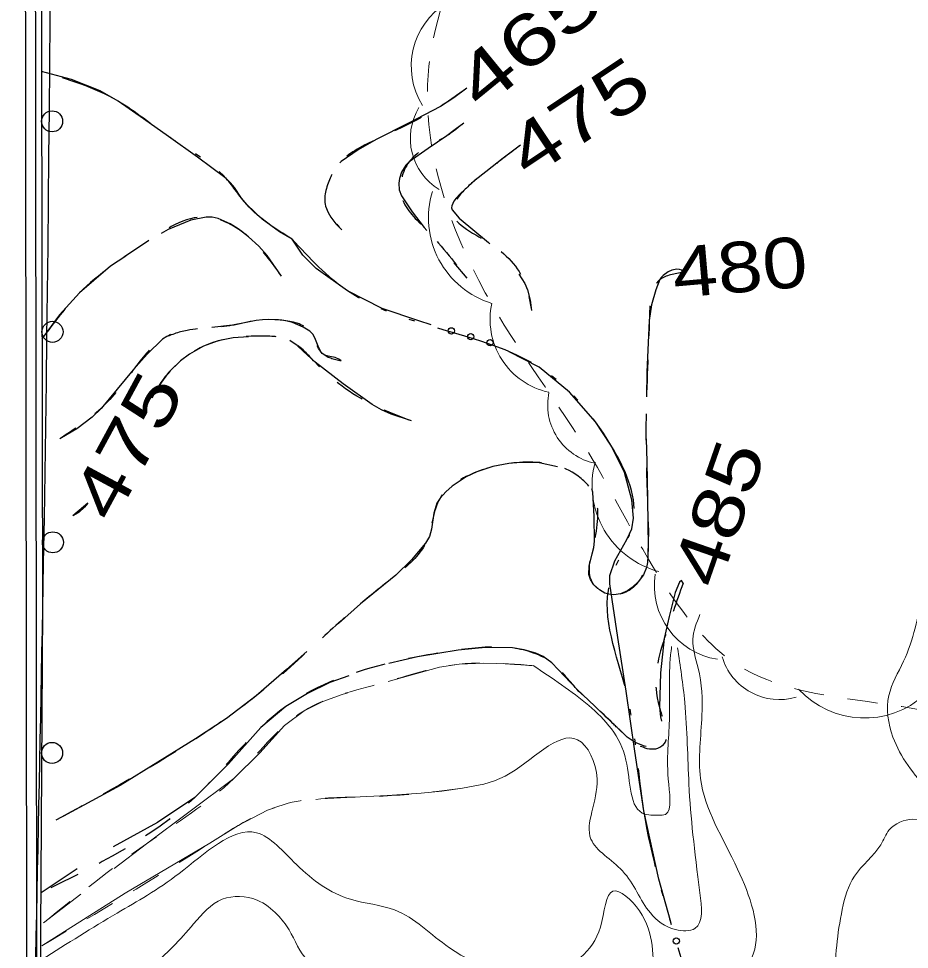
# Model space of a CAD drawing. Extents: x 2362213 to 2366494, y 6968794 to 6978110.
# Drawn here: x 2364480.8 to 2364565.4, y 6970408.1 to 6970496.6 of the extents above; entities that cross this region are included whole.
import ezdxf
from ezdxf.enums import TextEntityAlignment as Align

# ---------------------------------------------------------------- set-up
doc = ezdxf.new("R2010")
doc.units = 0
doc.header["$LTSCALE"] = 1.9
doc.linetypes.add('DASH_DOUBLE_DOT', pattern=[9.2, 5, -1.2, 0.3, -1.2, 0.3, -1.2])
doc.linetypes.add('SHORT_DASHED', pattern=[2.7, 1.5, -1.2])
for name, color, linetype, lineweight in [('2', 7, 'Continuous', 25), ('25', 7, 'Continuous', 25), ('29', 7, 'Continuous', 13), ('31', 7, 'Continuous', 25), ('32', 7, 'Continuous', 25), ('35', 7, 'Continuous', 13), ('36', 7, 'Continuous', 13), ('4', 7, 'Continuous', 25)]:
    doc.layers.add(name, color=color, linetype=linetype, lineweight=lineweight)

msp = doc.modelspace()

# ---------------------------------------------------------------- linework, layer by layer
at = {"layer": '2'}
for points in [[(2364480.853, 6970987.21), (2364481.694, 6970308.696), (2364482.198, 6970284.09)], [(2364481.813, 6970987.209), (2364482.654, 6970308.705), (2364483.158, 6970284.109), (2364483.158, 6970284.077)]]:
    msp.add_lwpolyline(points, dxfattribs=at)
at = {"layer": '25'}
for points in [[(2364506.806, 6970475.613), (2364505.599, 6970476.301), (2364503.978, 6970477.506), (2364502.504, 6970478.892), (2364501.998, 6970479.507), (2364501.329, 6970480.501), (2364500.965, 6970480.967), (2364500.541, 6970481.363), (2364497.821, 6970483.377), (2364495.072, 6970485.351), (2364492.685, 6970487.049), (2364490.279, 6970488.717), (2364488.591, 6970489.691), (2364485.871, 6970490.765), (2364483.013, 6970491.538)], [(2364520.034, 6970467.469), (2364518.839, 6970467.838), (2364515.358, 6970469.025), (2364512.073, 6970470.694), (2364509.103, 6970472.815), (2364507.83, 6970474.092), (2364506.806, 6970475.613)], [(2364542.764, 6970410.832), (2364541.646, 6970414.802), (2364540.234, 6970421.289), (2364539.379, 6970426.972), (2364538.535, 6970432.663), (2364537.757, 6970437.756), (2364536.978, 6970442.848), (2364536.98, 6970443.66), (2364537.457, 6970445.044), (2364538.618, 6970447.075), (2364539.078, 6970448.08), (2364539.249, 6970449.101), (2364539.082, 6970450.829), (2364538.367, 6970453.442), (2364537.083, 6970456.04), (2364535.612, 6970458.256), (2364533.165, 6970461.073), (2364530.273, 6970463.446), (2364527.419, 6970464.898)]]:
    msp.add_lwpolyline(points, dxfattribs=at)
for centre in [(2364521.935, 6970466.891), (2364523.772, 6970466.333), (2364525.609, 6970465.774), (2364543.301, 6970408.919)]:
    msp.add_circle(centre, 0.3, dxfattribs=at)
at = {"layer": '25', "linetype": 'DASH_DOUBLE_DOT'}
for points in [[(2364506.806, 6970475.613), (2364502.504, 6970478.892), (2364500.541, 6970481.363), (2364495.072, 6970485.351), (2364490.279, 6970488.717), (2364483.013, 6970491.538)], [(2364529.215, 6970111.429), (2364533.025, 6970126.065), (2364541.5, 6970141.398), (2364547.183, 6970152.691), (2364554.459, 6970169.883), (2364556.647, 6970182.694), (2364557.522, 6970196.872), (2364559.003, 6970231.429), (2364558, 6970252.81), (2364558.958, 6970261.44), (2364564.81, 6970286.446), (2364562.406, 6970307.734), (2364563.02, 6970328.261), (2364562.413, 6970346.906), (2364557.377, 6970364.359), (2364555.025, 6970370.947), (2364548.553, 6970391.056), (2364543.447, 6970408.398), (2364540.234, 6970421.289), (2364538.535, 6970432.663), (2364536.978, 6970442.848), (2364539.249, 6970449.101), (2364537.083, 6970456.04), (2364530.273, 6970463.446), (2364512.073, 6970470.694), (2364506.806, 6970475.613)]]:
    msp.add_spline(points, degree=3, dxfattribs=at)
at = {"layer": '29'}
for centre, radius, start, end in [((2364525.221, 6970492.025), 7.092, 121.74425, 211.74425), ((2364523.71, 6970485.177), 5.668, 148.92604, 238.92604), ((2364528.273, 6970477.633), 8.506, 162.93804, 252.93804), ((2364532.707, 6970467.983), 7.092, 167.6135, 257.6135), ((2364536.753, 6970459.854), 5.668, 167.91158, 257.91158), ((2364543.813, 6970452.243), 8.506, 165.25567, 255.25567), ((2364548.305, 6970442.696), 7.092, 171.14823, 261.14823), ((2364553.093, 6970437.524), 5.668, 196.36627, 286.36627), ((2364561.176, 6970438.612), 8.506, 222.53192, 312.53192)]:
    msp.add_arc(centre, radius, start, end, dxfattribs=at)
at = {"layer": '29', "linetype": 'SHORT_DASHED'}
msp.add_spline([(2365019.344, 6970741.976), (2365013.583, 6970748.262), (2365003.35, 6970744.224), (2364989.177, 6970735.179), (2364981.124, 6970725.912), (2364978.952, 6970711.4), (2364989.669, 6970697.142), (2365002.522, 6970686.285), (2365003.085, 6970672.298), (2364993.278, 6970662.614), (2364980.234, 6970648.13), (2364962.83, 6970612.932), (2364946.985, 6970580.76), (2364933.414, 6970542.959), (2364930.334, 6970505.147), (2364923.417, 6970477.53), (2364897.761, 6970466.516), (2364866.188, 6970470.776), (2364836.123, 6970473.349), (2364795.817, 6970475.796), (2364767.656, 6970480.077), (2364748.092, 6970503.421), (2364708.874, 6970477.837), (2364679.431, 6970464.306), (2364646.865, 6970444.886), (2364624.431, 6970430.481), (2364612.969, 6970400.141), (2364604.826, 6970354.251), (2364605.553, 6970317.806), (2364606.592, 6970290.644), (2364601.528, 6970267.945), (2364588.81, 6970268.694), (2364579.544, 6970276.606), (2364580.363, 6970312.406), (2364581.871, 6970360.932), (2364581.995, 6970404.655), (2364573.318, 6970428.424), (2364549.103, 6970435.154), (2364543.286, 6970441.098), (2364535.306, 6970454.743), (2364525.155, 6970470.518), (2364519.677, 6970490.277), (2364530.681, 6970517.193), (2364547.703, 6970543.275), (2364568.076, 6970553.571), (2364584.707, 6970547.148), (2364614.664, 6970561.425), (2364638.924, 6970579.316), (2364671.914, 6970607.812), (2364684.38, 6970620.921), (2364713.797, 6970629.752), (2364754.136, 6970656.387), (2364756.635, 6970676.392), (2364760.896, 6970685.742), (2364783.651, 6970704.25), (2364813.03, 6970713.99), (2364839.877, 6970707.106), (2364862.329, 6970704.859), (2364897.161, 6970715.382), (2364909.564, 6970730.761), (2364927.94, 6970754.397), (2364941.131, 6970774.483), (2364947.076, 6970797.082), (2364974.605, 6970816.044), (2364994.111, 6970824.041), (2365019.18, 6970841.1)], degree=3, dxfattribs=at)
at = {"layer": '31'}
msp.add_spline([(2364483.036, 6970393.543), (2364485.975, 6970394.721), (2364489.782, 6970395.077), (2364495.397, 6970396.52), (2364499.407, 6970396.689), (2364502.422, 6970395.127), (2364505.902, 6970392.04), (2364512.075, 6970387.479), (2364517.801, 6970385.743), (2364523.937, 6970383.132), (2364532.351, 6970380.652), (2364538.596, 6970377.992), (2364543.863, 6970374.191), (2364547.892, 6970368.059), (2364550.864, 6970356.298), (2364553.114, 6970349.978), (2364554.659, 6970345.302), (2364557.035, 6970338.355), (2364557.926, 6970334.074), (2364558.007, 6970324.463), (2364558.363, 6970316.546), (2364558.641, 6970314.589), (2364560.103, 6970314.403), (2364561.94, 6970310.401), (2364563.402, 6970307.254), (2364565.244, 6970308.061), (2364566.132, 6970314.61), (2364566.812, 6970326.107), (2364567.995, 6970334.25), (2364569.194, 6970344.791), (2364569.453, 6970350.213), (2364568.571, 6970358.745), (2364566.228, 6970369.584), (2364565.213, 6970377.415), (2364565.146, 6970386.574), (2364567.058, 6970389.572), (2364569.226, 6970391.833), (2364571.962, 6970394.449), (2364572.865, 6970397.208), (2364573.496, 6970404.494), (2364577.22, 6970410.39), (2364586.953, 6970409.043)], degree=3, dxfattribs=at)
at = {"layer": '32'}
for p, q in [((2364522.158, 6970473.339), (2364523.402, 6970471.901)), ((2364486.405, 6970415.776), (2364482.966, 6970413.513))]:
    msp.add_line(p, q, dxfattribs=at)
at = {"layer": '32', "linetype": 'SHORT_DASHED'}
msp.add_line((2364487.414, 6970450.527), (2364485.985, 6970449.314), dxfattribs=at)
at = {"layer": '32'}
for points in [[(2364523.4, 6970489.942), (2364522.179, 6970489.041), (2364520.896, 6970488.218), (2364517.87, 6970486.618), (2364514.805, 6970485.079), (2364513.094, 6970484.103), (2364511.456, 6970482.967), (2364511.357, 6970482.866)], [(2364523.112, 6970486.638), (2364522.307, 6970486.021), (2364521.503, 6970485.413), (2364519.724, 6970484.216), (2364517.935, 6970482.959), (2364517.628, 6970482.646), (2364517.205, 6970481.962), (2364517.01, 6970481.38), (2364516.945, 6970480.929), (2364516.981, 6970480.28), (2364517.196, 6970479.712), (2364518.221, 6970478.191), (2364519.356, 6970476.712), (2364519.599, 6970476.414)], [(2364528.502, 6970484.54), (2364526.844, 6970483.284), (2364525.206, 6970482.008), (2364524.213, 6970481.199), (2364523.242, 6970480.339), (2364522.766, 6970479.895), (2364522.399, 6970479.511), (2364522.172, 6970479.209), (2364521.976, 6970478.777), (2364521.958, 6970478.577), (2364522.02, 6970478.398), (2364522.688, 6970477.594), (2364525.46, 6970475.28), (2364525.591, 6970475.151)], [(2364509.911, 6970479.232), (2364509.913, 6970479.102), (2364509.986, 6970478.743), (2364510.222, 6970478.125), (2364510.476, 6970477.678), (2364510.962, 6970477.052), (2364511.548, 6970476.488)], [(2364505.789, 6970472.094), (2364504.451, 6970474.05), (2364503.642, 6970474.942), (2364502.674, 6970475.823), (2364501.686, 6970476.584), (2364500.932, 6970477.067), (2364499.787, 6970477.576), (2364499.206, 6970477.69), (2364498.635, 6970477.705), (2364497.198, 6970477.421), (2364495.026, 6970476.51), (2364494.389, 6970476.134)], [(2364491.009, 6970474.002), (2364489.559, 6970473.038), (2364486.614, 6970470.501), (2364484.723, 6970468.403), (2364483.055, 6970466.137)], [(2364528.359, 6970472.269), (2364528.917, 6970471.404), (2364529.173, 6970470.786), (2364529.412, 6970469.819), (2364529.561, 6970468.84)], [(2364543.998, 6970472.448), (2364543.826, 6970472.646), (2364543.595, 6970472.734), (2364543.355, 6970472.752), (2364542.886, 6970472.647), (2364542.527, 6970472.494), (2364542.05, 6970472.159), (2364541.872, 6970471.967), (2364541.744, 6970471.756), (2364541.353, 6970470.802), (2364540.936, 6970469.358), (2364540.74, 6970467.886), (2364540.507, 6970462.953), (2364540.469, 6970460.623)], [(2364511.476, 6970464.027), (2364511.305, 6970464.185), (2364510.913, 6970464.361), (2364510.232, 6970464.495), (2364509.921, 6970464.592), (2364509.669, 6970464.749), (2364509.497, 6970464.968), (2364509.273, 6970465.447), (2364508.975, 6970466.234), (2364508.772, 6970466.582), (2364508.479, 6970466.859), (2364507.846, 6970467.243), (2364506.861, 6970467.674), (2364506.35, 6970467.809), (2364505.829, 6970467.894), (2364504.609, 6970467.962), (2364503.999, 6970467.937), (2364503.399, 6970467.871), (2364502.281, 6970467.64), (2364501.164, 6970467.42), (2364499.196, 6970467.201)], [(2364495.261, 6970466.533), (2364494.902, 6970466.36), (2364494.505, 6970466.086), (2364493.038, 6970464.681), (2364491.722, 6970463.178), (2364490.21, 6970461.354), (2364488.668, 6970459.529), (2364487.806, 6970458.681), (2364486.366, 6970457.587), (2364484.746, 6970456.632)], [(2364502.674, 6970466.324), (2364501.205, 6970466.24), (2364499.797, 6970465.956), (2364498.382, 6970465.423), (2364497.079, 6970464.69), (2364496.204, 6970464.051), (2364495.075, 6970462.95), (2364494.147, 6970461.671), (2364493.802, 6970461.088), (2364493.478, 6970460.495)], [(2364518.16, 6970458.33), (2364516.224, 6970458.962), (2364515.3, 6970459.373), (2364514.415, 6970459.884), (2364511.647, 6970461.848), (2364508.987, 6970463.903), (2364507.867, 6970464.962), (2364507.282, 6970465.498), (2364506.597, 6970465.981)], [(2364540.447, 6970456.622), (2364540.488, 6970454.442), (2364540.562, 6970450.873), (2364540.593, 6970448.614), (2364540.615, 6970446.344), (2364540.613, 6970445.494), (2364540.569, 6970444.874), (2364540.473, 6970444.413), (2364540.2, 6970443.72), (2364539.696, 6970443.035), (2364539.112, 6970442.499), (2364538.674, 6970442.205), (2364538.017, 6970441.918), (2364537.358, 6970441.822), (2364536.887, 6970441.868), (2364536.526, 6970441.974), (2364535.995, 6970442.279), (2364535.48, 6970442.764), (2364535.145, 6970443.282), (2364535.001, 6970443.731), (2364535.013, 6970444.521), (2364535.312, 6970445.714), (2364535.466, 6970446.315), (2364535.52, 6970446.906), (2364535.508, 6970449.246), (2364535.366, 6970451.573), (2364535.283, 6970451.883)], [(2364532.013, 6970453.982), (2364530.269, 6970454.345), (2364528.399, 6970454.387), (2364527.39, 6970454.298), (2364525.872, 6970454.003), (2364524.357, 6970453.489), (2364523.352, 6970453.019), (2364522.02, 6970452.146), (2364521.415, 6970451.611), (2364520.861, 6970450.995), (2364520.555, 6970450.512), (2364520.264, 6970449.561), (2364520.039, 6970448.058), (2364519.846, 6970447.347), (2364519.491, 6970446.723), (2364518.156, 6970445.13), (2364516.669, 6970443.686), (2364514.972, 6970442.329), (2364513.305, 6970440.953), (2364511.224, 6970439.093), (2364511.204, 6970439.073)], [(2364487.414, 6970450.527), (2364487.107, 6970450.154), (2364486.572, 6970449.66), (2364486.284, 6970449.467), (2364485.985, 6970449.314)], [(2364543.949, 6970442.915), (2364543.786, 6970443.174), (2364543.598, 6970443.002), (2364543.207, 6970442.038), (2364542.609, 6970439.762), (2364542.159, 6970437.658), (2364541.8, 6970434.394), (2364541.691, 6970431.123), (2364541.79, 6970430.214), (2364541.884, 6970429.805)], [(2364540.425, 6970427.401), (2364540.295, 6970427.419), (2364539.402, 6970427.771), (2364538.637, 6970428.304), (2364537.96, 6970428.957), (2364537.284, 6970429.601), (2364535.56, 6970431.224), (2364533.844, 6970432.858), (2364532.692, 6970434.097), (2364531.49, 6970435.346), (2364530.655, 6970435.938), (2364529.961, 6970436.271), (2364528.868, 6970436.601), (2364527.747, 6970436.76), (2364525.166, 6970436.796), (2364522.588, 6970436.561), (2364518.733, 6970435.924), (2364516.009, 6970435.298)], [(2364508.219, 6970436.414), (2364506.275, 6970434.706), (2364503.389, 6970432.208), (2364500.589, 6970430.071), (2364497.648, 6970428.123), (2364490.468, 6970423.696), (2364485.097, 6970420.783)], [(2364512.201, 6970434.102), (2364510.407, 6970433.485), (2364508.267, 6970432.445), (2364506.209, 6970431.205), (2364503.847, 6970429.222), (2364500.78, 6970425.764), (2364497.561, 6970422.553), (2364494.012, 6970420.188), (2364489.815, 6970417.858)]]:
    msp.add_lwpolyline(points, dxfattribs=at)
at = {"layer": '32', "linetype": 'SHORT_DASHED'}
for points in [[(2364523.4, 6970489.942), (2364520.896, 6970488.218), (2364514.805, 6970485.079), (2364511.456, 6970482.967), (2364510.431, 6970481.407), (2364509.986, 6970478.743), (2364511.548, 6970476.488)], [(2364523.112, 6970486.638), (2364521.503, 6970485.413), (2364517.935, 6970482.959), (2364517.196, 6970479.712), (2364519.356, 6970476.712), (2364523.402, 6970471.901)], [(2364528.502, 6970484.54), (2364525.206, 6970482.008), (2364523.242, 6970480.339), (2364522.02, 6970478.398), (2364525.46, 6970475.28), (2364528.917, 6970471.404), (2364529.561, 6970468.84)], [(2364505.789, 6970472.094), (2364502.674, 6970475.823), (2364498.635, 6970477.705), (2364492.877, 6970475.26), (2364486.614, 6970470.501), (2364483.055, 6970466.137)], [(2364543.998, 6970472.448), (2364541.744, 6970471.756), (2364540.74, 6970467.886), (2364540.424, 6970458.012), (2364540.562, 6970450.873), (2364540.615, 6970446.344), (2364539.696, 6970443.035), (2364537.358, 6970441.822), (2364535.48, 6970442.764), (2364535.52, 6970446.906), (2364535.366, 6970451.573), (2364533.408, 6970453.455), (2364528.399, 6970454.387), (2364524.357, 6970453.489), (2364520.861, 6970450.995), (2364519.491, 6970446.723), (2364516.669, 6970443.686), (2364513.305, 6970440.953), (2364509.141, 6970437.233), (2364503.389, 6970432.208), (2364497.648, 6970428.123), (2364483.067, 6970419.684)], [(2364511.476, 6970464.027), (2364509.669, 6970464.749), (2364508.479, 6970466.859), (2364505.829, 6970467.894), (2364503.399, 6970467.871), (2364501.164, 6970467.42), (2364496.838, 6970466.938), (2364494.505, 6970466.086), (2364491.722, 6970463.178), (2364488.668, 6970459.529), (2364484.746, 6970456.632)], [(2364518.16, 6970458.33), (2364514.415, 6970459.884), (2364508.987, 6970463.903), (2364506.587, 6970465.991), (2364504.043, 6970466.397), (2364498.382, 6970465.423), (2364494.147, 6970461.671), (2364493.478, 6970460.495)], [(2364543.949, 6970442.915), (2364542.159, 6970437.658), (2364541.691, 6970431.123), (2364541.986, 6970427.495), (2364541.697, 6970427.293), (2364538.637, 6970428.304), (2364537.284, 6970429.601), (2364533.844, 6970432.858), (2364531.49, 6970435.346), (2364527.747, 6970436.76), (2364522.588, 6970436.561), (2364514.911, 6970435.048), (2364506.209, 6970431.205), (2364497.561, 6970422.553), (2364482.966, 6970413.513)]]:
    msp.add_spline(points, degree=3, dxfattribs=at)
at = {"layer": '35'}
for points in [[(2364579.387, 6970412.791), (2364576.164, 6970414.12), (2364573.159, 6970416.832), (2364567.218, 6970423.207), (2364563.879, 6970428.304), (2364563.491, 6970432.25), (2364564.89, 6970435.504), (2364566.68, 6970441.891)], [(2364545.547, 6970439.94), (2364544.87, 6970437.593), (2364545.376, 6970434.858), (2364545.738, 6970430.361), (2364545.595, 6970424.371), (2364549.128, 6970415.753), (2364550.75, 6970408.138), (2364547.678, 6970402.019), (2364545.977, 6970398.002), (2364542.472, 6970401.61), (2364541.217, 6970405.307), (2364539.804, 6970411.794), (2364537.286, 6970413.66), (2364536.09, 6970410.249), (2364531.35, 6970405.993), (2364521.748, 6970408.282), (2364516.542, 6970411.872), (2364512.363, 6970412.883), (2364507.222, 6970416.194), (2364503.433, 6970419.208), (2364496.068, 6970415.328), (2364490.184, 6970411.571), (2364483.056, 6970407.163)], [(2364543.417, 6970436.769), (2364544.107, 6970431.596), (2364544.5, 6970423.85), (2364545.539, 6970413.509), (2364545.071, 6970410.114), (2364543.222, 6970410.006), (2364540.836, 6970411.584), (2364538.188, 6970415.579), (2364535.2, 6970418.6), (2364535.775, 6970424.327), (2364533.92, 6970428.049), (2364527.053, 6970424.594), (2364523.003, 6970423.455)], [(2364542.856, 6970436.904), (2364542.764, 6970436.103), (2364542.653, 6970429.902), (2364542.581, 6970423.812), (2364541.959, 6970420.876), (2364541.929, 6970420.876), (2364540.327, 6970420.97), (2364538.518, 6970426.113), (2364534.979, 6970431.289), (2364529.713, 6970435.089)], [(2364579.472, 6970411.222), (2364576.411, 6970411.363), (2364574.43, 6970411.464), (2364572.489, 6970413.655), (2364571.24, 6970417.704), (2364569.408, 6970419.016), (2364565.763, 6970420.502), (2364563.533, 6970419.47), (2364562.715, 6970418.072), (2364560.214, 6970415.088), (2364559.065, 6970411.927), (2364558.37, 6970405.02), (2364558.274, 6970399.42), (2364557.186, 6970394.999), (2364555.351, 6970392.381), (2364554.513, 6970392.133), (2364552.569, 6970392.515), (2364551.614, 6970394.076), (2364550.335, 6970399.275), (2364548.719, 6970400.899), (2364547.616, 6970399.169), (2364547.248, 6970392.564), (2364546.417, 6970391.646), (2364542.797, 6970392.642), (2364540.73, 6970395.432), (2364537.514, 6970396.071), (2364533.763, 6970396.236), (2364525.969, 6970396.602), (2364519.506, 6970397.91), (2364514.13, 6970401.58), (2364512.361, 6970404.742), (2364508.298, 6970407.074), (2364506.521, 6970409.987), (2364505.417, 6970411.416), (2364503.484, 6970412.808), (2364500.183, 6970412.887), (2364497.455, 6970410.551), (2364493.372, 6970406.512), (2364483.046, 6970402.984)]]:
    msp.add_spline(points, degree=3, dxfattribs=at)
at = {"layer": '36'}
msp.add_line((2364486.737, 6970413.379), (2364483.213, 6970410.655), dxfattribs=at)
for points in [[(2364529.733, 6970435.079), (2364528.542, 6970435.178), (2364527.351, 6970435.246), (2364525.01, 6970435.334), (2364522.681, 6970435.232), (2364520.824, 6970434.934), (2364515.945, 6970433.588)], [(2364512.097, 6970432.491), (2364511.578, 6970432.346), (2364509.724, 6970431.678), (2364507.943, 6970430.801), (2364506.096, 6970429.394), (2364503.75, 6970426.801), (2364501.273, 6970424.369), (2364497.123, 6970421.269), (2364492.971, 6970418.158), (2364489.913, 6970415.819)], [(2364523.003, 6970423.455), (2364521.036, 6970423.167), (2364519.058, 6970422.958), (2364515.848, 6970422.757), (2364512.631, 6970422.597), (2364509.532, 6970422.427), (2364509.053, 6970422.363)], [(2364505.14, 6970421.585), (2364504.462, 6970421.359), (2364501.696, 6970419.881), (2364499.012, 6970418.226), (2364490.956, 6970413.459), (2364483.054, 6970408.463)]]:
    msp.add_lwpolyline(points, dxfattribs=at)
at = {"layer": '36', "linetype": 'SHORT_DASHED'}
for points in [[(2364529.733, 6970435.079), (2364527.351, 6970435.246), (2364522.681, 6970435.232), (2364515.377, 6970433.432), (2364507.943, 6970430.801), (2364501.273, 6970424.369), (2364492.971, 6970418.158), (2364483.213, 6970410.655)], [(2364523.003, 6970423.455), (2364519.058, 6970422.958), (2364512.631, 6970422.597), (2364506.446, 6970422.008), (2364499.012, 6970418.226), (2364483.054, 6970408.463)]]:
    msp.add_spline(points, degree=3, dxfattribs=at)
at = {"layer": '4'}
msp.add_lwpolyline([(2364481.56, 6971076.78), (2364482.301, 6971053.546), (2364482.593, 6971030.318), (2364482.362, 6971006.186), (2364482.172, 6970982.043), (2364482.381, 6970848.818), (2364482.609, 6970715.594), (2364482.849, 6970578.05), (2364483.099, 6970440.505), (2364482.681, 6970374.168), (2364482.922, 6970307.848), (2364483.755, 6970291.775), (2364484.938, 6970275.715), (2364486.154, 6970258.266), (2364487.321, 6970240.805), (2364488.08, 6970216.783), (2364488.435, 6970208.727)], dxfattribs=at)
for centre in [(2364484.016, 6970486.798), (2364484.052, 6970466.798), (2364484.087, 6970446.798), (2364484.012, 6970426.79)]:
    msp.add_circle(centre, 1, dxfattribs=at)
msp.add_spline([(2364481.56, 6971076.78), (2364482.593, 6971030.318), (2364482.172, 6970982.043), (2364482.609, 6970715.594), (2364483.099, 6970440.505), (2364482.922, 6970307.848), (2364484.938, 6970275.715), (2364487.321, 6970240.805), (2364488.678, 6970192.747), (2364490.444, 6970156.442), (2364492.883, 6970112.344)], degree=3, dxfattribs=at)

# ---------------------------------------------------------------- texts
at = {"layer": '31'}
for s, rotation, width, p in [(' 465 ', 39.27, 1.45, (2364530.759, 6970492.639)), (' 475 ', 33.607, 1.35, (2364535.293, 6970485.225)), (' 480 ', 5.003, 1.2, (2364549.544, 6970470.569)), (' 475 ', 61.568, 1.35, (2364493.266, 6970454.834)), (' 485 ', 70.789, 1.3, (2364549.577, 6970448.794))]:
    msp.add_text(s, height=4.8, rotation=rotation, dxfattribs=dict(at, width=width)).set_placement(p, align=Align.CENTER)

doc.saveas('drawing.dxf')
